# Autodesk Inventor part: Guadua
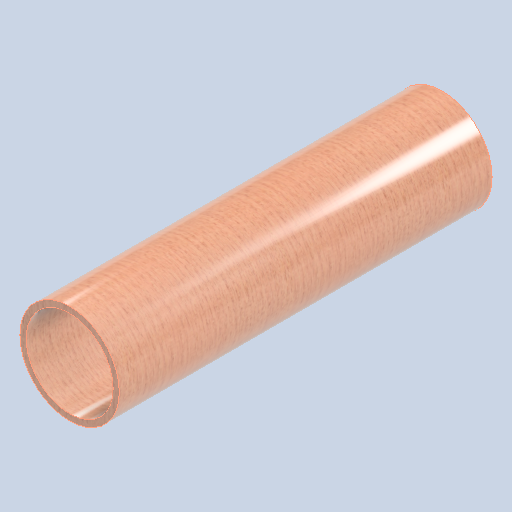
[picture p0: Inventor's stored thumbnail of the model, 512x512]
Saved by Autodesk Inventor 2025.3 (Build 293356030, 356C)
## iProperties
Created: 2025-09
Part Number: Guadua
Material: Wood (Oak)
Document SubType Name: Modeling
Designer: User
Density: 0.76 g/cm^3
Appearance: White Oak - Natural Medium Gloss
Author: User
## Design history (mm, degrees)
sketch "Boceto1"
  geometry: C1 r 80 at (0, 0); 1 further point
  constraints: 1 centre point, 1 coincident
  dimensions: "d0" = 160 diameter of C1
extrude "Extrusión1" new body sketch "Boceto1" distance "d1" = 600; taper "d2" = 0 deg
sketch "Boceto2"
  geometry: 2 further points
  constraints: 1 coincident
hole "Agujero1" sketch "Boceto2" at (0, 0) diameter "d3" = 140; stored, may be unused: countersink angle "d7" = 90 deg, drill point angle "d9" = 0 deg; dims "d4" = 6, "d5" = 4, "d6" = 2, "d8" = 31.296
node "Sólido1"
node "Acabados"
node "Finish4" dims "Finish4_Area" = 57491.14556
